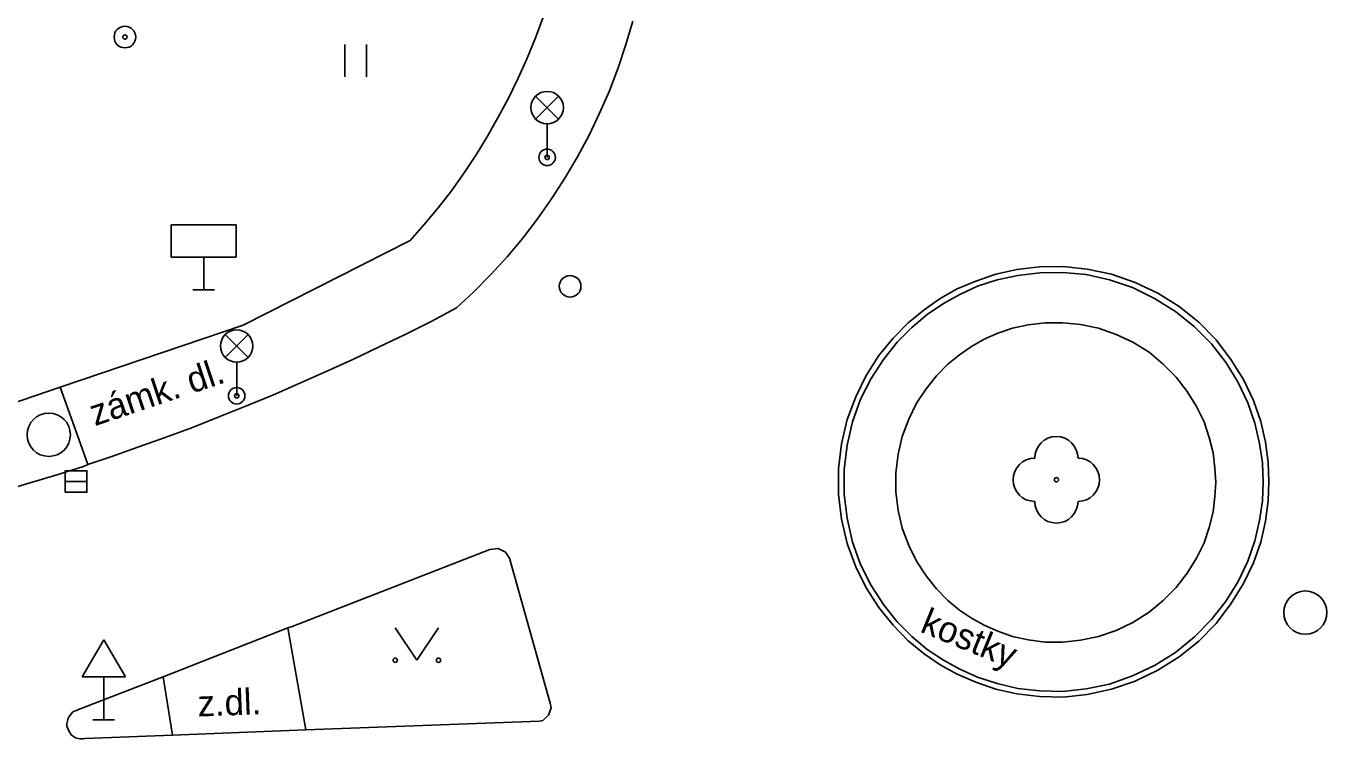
# Model space of a CAD drawing. Extents: x -493753 to -49290, y -1127285 to -112654.
# Drawn here: x -493551.62 to -493521.58, y -1126786.62 to -1126770.15 of the extents above; entities that cross this region are included whole.
import ezdxf

# ---------------------------------------------------------------- set-up
doc = ezdxf.new("R2010")
doc.units = 0
for name, color, linetype in [('Vrstva 10', 7, 'Continuous'), ('Vrstva 11', 7, 'Continuous'), ('Vrstva 22', 7, 'Continuous'), ('Vrstva 25', 7, 'Continuous'), ('Vrstva 27', 7, 'Continuous'), ('Vrstva 31', 7, 'Continuous'), ('Vrstva 33', 7, 'Continuous'), ('Vrstva 34', 7, 'Continuous'), ('Vrstva 36', 7, 'Continuous'), ('Vrstva 40', 7, 'Continuous')]:
    doc.layers.add(name, color=color, linetype=linetype)

msp = doc.modelspace()

# ---------------------------------------------------------------- linework, layer by layer
at = {"layer": 'Vrstva 10'}
for p, q in [((-493539.86, -1126770.42), (-493539.68, -1126769.94)), ((-493537.77, -1126770.57), (-493537.61, -1126770.03)), ((-493540.05, -1126770.89), (-493539.86, -1126770.42)), ((-493537.95, -1126771.11), (-493537.77, -1126770.57)), ((-493540.26, -1126771.35), (-493540.05, -1126770.89)), ((-493538.15, -1126771.64), (-493537.95, -1126771.11)), ((-493540.48, -1126771.81), (-493540.26, -1126771.35)), ((-493540.72, -1126772.25), (-493540.48, -1126771.81)), ((-493538.38, -1126772.16), (-493538.15, -1126771.64)), ((-493538.62, -1126772.67), (-493538.38, -1126772.16)), ((-493540.97, -1126772.69), (-493540.72, -1126772.25)), ((-493541.23, -1126773.12), (-493540.97, -1126772.69)), ((-493538.89, -1126773.17), (-493538.62, -1126772.67)), ((-493541.51, -1126773.54), (-493541.23, -1126773.12)), ((-493539.18, -1126773.66), (-493538.89, -1126773.17)), ((-493541.8, -1126773.95), (-493541.51, -1126773.54)), ((-493539.49, -1126774.14), (-493539.18, -1126773.66)), ((-493542.11, -1126774.35), (-493541.8, -1126773.95)), ((-493539.81, -1126774.6), (-493539.49, -1126774.14)), ((-493542.43, -1126774.73), (-493542.11, -1126774.35)), ((-493540.15, -1126775.05), (-493539.81, -1126774.6)), ((-493542.75, -1126775.1), (-493542.43, -1126774.73)), ((-493546.61, -1126777.06), (-493542.75, -1126775.1)), ((-493540.51, -1126775.48), (-493540.15, -1126775.05)), ((-493540.89, -1126775.89), (-493540.51, -1126775.48)), ((-493528.74, -1126775.77), (-493529.23, -1126775.88)), ((-493528.22, -1126775.71), (-493528.74, -1126775.77)), ((-493527.67, -1126775.7), (-493528.22, -1126775.71)), ((-493527.12, -1126775.76), (-493527.67, -1126775.7)), ((-493526.56, -1126775.88), (-493527.12, -1126775.76)), ((-493541.28, -1126776.29), (-493540.89, -1126775.89)), ((-493529.69, -1126776.04), (-493530.12, -1126776.22)), ((-493529.23, -1126775.88), (-493529.69, -1126776.04)), ((-493526.01, -1126776.07), (-493526.56, -1126775.88)), ((-493525.49, -1126776.32), (-493526.01, -1126776.07)), ((-493541.68, -1126776.66), (-493541.28, -1126776.29)), ((-493530.12, -1126776.22), (-493530.51, -1126776.44)), ((-493524.99, -1126776.63), (-493525.49, -1126776.32)), ((-493542.27, -1126776.97), (-493541.68, -1126776.66)), ((-493530.88, -1126776.7), (-493531.25, -1126777)), ((-493530.51, -1126776.44), (-493530.88, -1126776.7)), ((-493524.54, -1126776.99), (-493524.99, -1126776.63)), ((-493542.87, -1126777.27), (-493542.27, -1126776.97)), ((-493531.25, -1126777), (-493531.6, -1126777.36)), ((-493528.09, -1126777), (-493528.48, -1126777.05)), ((-493527.68, -1126777), (-493528.09, -1126777)), ((-493527.27, -1126777.04), (-493527.68, -1126777)), ((-493524.14, -1126777.4), (-493524.54, -1126776.99)), ((-493550.84, -1126778.49), (-493546.61, -1126777.06)), ((-493543.47, -1126777.56), (-493542.87, -1126777.27)), ((-493529.18, -1126777.24), (-493529.5, -1126777.38)), ((-493528.84, -1126777.13), (-493529.18, -1126777.24)), ((-493528.48, -1126777.05), (-493528.84, -1126777.13)), ((-493526.86, -1126777.13), (-493527.27, -1126777.04)), ((-493526.45, -1126777.27), (-493526.86, -1126777.13)), ((-493526.06, -1126777.45), (-493526.45, -1126777.27)), ((-493544.08, -1126777.85), (-493543.47, -1126777.56)), ((-493531.6, -1126777.36), (-493531.93, -1126777.76)), ((-493529.79, -1126777.55), (-493530.07, -1126777.74)), ((-493529.5, -1126777.38), (-493529.79, -1126777.55)), ((-493525.69, -1126777.68), (-493526.06, -1126777.45)), ((-493523.8, -1126777.85), (-493524.14, -1126777.4)), ((-493544.69, -1126778.13), (-493544.08, -1126777.85)), ((-493531.93, -1126777.76), (-493532.22, -1126778.22)), ((-493530.07, -1126777.74), (-493530.34, -1126777.96)), ((-493525.36, -1126777.96), (-493525.69, -1126777.68)), ((-493523.51, -1126778.31), (-493523.8, -1126777.85)), ((-493545.3, -1126778.4), (-493544.69, -1126778.13)), ((-493532.22, -1126778.22), (-493532.46, -1126778.71)), ((-493530.6, -1126778.23), (-493530.84, -1126778.53)), ((-493530.34, -1126777.96), (-493530.6, -1126778.23)), ((-493525.06, -1126778.26), (-493525.36, -1126777.96)), ((-493554.13, -1126779.61), (-493550.84, -1126778.49)), ((-493545.91, -1126778.67), (-493545.3, -1126778.4)), ((-493530.84, -1126778.53), (-493531.06, -1126778.86)), ((-493524.81, -1126778.59), (-493525.06, -1126778.26)), ((-493523.28, -1126778.8), (-493523.51, -1126778.31)), ((-493546.53, -1126778.92), (-493545.91, -1126778.67)), ((-493532.46, -1126778.71), (-493532.66, -1126779.24)), ((-493524.59, -1126778.94), (-493524.81, -1126778.59)), ((-493523.11, -1126779.28), (-493523.28, -1126778.8)), ((-493547.15, -1126779.17), (-493546.53, -1126778.92)), ((-493531.06, -1126778.86), (-493531.24, -1126779.23)), ((-493524.42, -1126779.29), (-493524.59, -1126778.94)), ((-493548.41, -1126779.65), (-493547.78, -1126779.42)), ((-493547.78, -1126779.42), (-493547.15, -1126779.17)), ((-493532.66, -1126779.24), (-493532.79, -1126779.8)), ((-493531.24, -1126779.23), (-493531.39, -1126779.63)), ((-493524.3, -1126779.65), (-493524.42, -1126779.29)), ((-493523, -1126779.76), (-493523.11, -1126779.28)), ((-493549.04, -1126779.88), (-493548.41, -1126779.65)), ((-493531.39, -1126779.63), (-493531.48, -1126780.04)), ((-493524.21, -1126780.01), (-493524.3, -1126779.65)), ((-493549.67, -1126780.1), (-493549.04, -1126779.88)), ((-493532.79, -1126779.8), (-493532.86, -1126780.38)), ((-493524.17, -1126780.36), (-493524.21, -1126780.01)), ((-493522.94, -1126780.23), (-493523, -1126779.76)), ((-493550.94, -1126780.52), (-493550.3, -1126780.32)), ((-493531.48, -1126780.04), (-493531.54, -1126780.47)), ((-493522.92, -1126780.67), (-493522.94, -1126780.23)), ((-493551.58, -1126780.72), (-493550.94, -1126780.52)), ((-493532.86, -1126780.38), (-493532.86, -1126780.97)), ((-493531.54, -1126780.47), (-493531.54, -1126780.91)), ((-493524.15, -1126780.69), (-493524.17, -1126780.36)), ((-493552.22, -1126780.91), (-493551.58, -1126780.72)), ((-493531.54, -1126780.91), (-493531.48, -1126781.34)), ((-493524.17, -1126781.02), (-493524.15, -1126780.69)), ((-493522.94, -1126781.12), (-493522.92, -1126780.67)), ((-493532.86, -1126780.97), (-493532.79, -1126781.54)), ((-493524.21, -1126781.37), (-493524.17, -1126781.02)), ((-493523, -1126781.59), (-493522.94, -1126781.12)), ((-493532.79, -1126781.54), (-493532.66, -1126782.1)), ((-493531.48, -1126781.34), (-493531.39, -1126781.75)), ((-493524.3, -1126781.73), (-493524.21, -1126781.37)), ((-493531.39, -1126781.75), (-493531.24, -1126782.15)), ((-493524.42, -1126782.09), (-493524.3, -1126781.73)), ((-493523.11, -1126782.07), (-493523, -1126781.59)), ((-493532.66, -1126782.1), (-493532.46, -1126782.64)), ((-493524.59, -1126782.44), (-493524.42, -1126782.09)), ((-493523.28, -1126782.55), (-493523.11, -1126782.07)), ((-493531.24, -1126782.15), (-493531.06, -1126782.51)), ((-493524.81, -1126782.79), (-493524.59, -1126782.44)), ((-493532.46, -1126782.64), (-493532.22, -1126783.13)), ((-493531.06, -1126782.51), (-493530.84, -1126782.85)), ((-493523.51, -1126783.03), (-493523.28, -1126782.55)), ((-493530.84, -1126782.85), (-493530.6, -1126783.15)), ((-493525.06, -1126783.12), (-493524.81, -1126782.79)), ((-493523.8, -1126783.5), (-493523.51, -1126783.03)), ((-493532.22, -1126783.13), (-493531.93, -1126783.58)), ((-493530.6, -1126783.15), (-493530.34, -1126783.42)), ((-493525.36, -1126783.42), (-493525.06, -1126783.12)), ((-493531.93, -1126783.58), (-493531.6, -1126783.99)), ((-493530.34, -1126783.42), (-493530.07, -1126783.64)), ((-493530.07, -1126783.64), (-493529.79, -1126783.83)), ((-493525.69, -1126783.69), (-493525.36, -1126783.42)), ((-493524.14, -1126783.95), (-493523.8, -1126783.5)), ((-493529.79, -1126783.83), (-493529.5, -1126783.99)), ((-493526.45, -1126784.11), (-493526.06, -1126783.93)), ((-493526.06, -1126783.93), (-493525.69, -1126783.69)), ((-493548.46, -1126785.18), (-493545.58, -1126784.05)), ((-493545.48, -1126784.02), (-493545.58, -1126784.05)), ((-493545.16, -1126786.41), (-493545.58, -1126784.05)), ((-493531.6, -1126783.99), (-493531.25, -1126784.35)), ((-493529.5, -1126783.99), (-493529.18, -1126784.13)), ((-493529.18, -1126784.13), (-493528.84, -1126784.25)), ((-493526.86, -1126784.25), (-493526.45, -1126784.11)), ((-493524.54, -1126784.36), (-493524.14, -1126783.95)), ((-493531.25, -1126784.35), (-493530.88, -1126784.65)), ((-493528.84, -1126784.25), (-493528.48, -1126784.33)), ((-493528.48, -1126784.33), (-493528.09, -1126784.38)), ((-493528.09, -1126784.38), (-493527.68, -1126784.38)), ((-493527.68, -1126784.38), (-493527.27, -1126784.34)), ((-493527.27, -1126784.34), (-493526.86, -1126784.25)), ((-493524.99, -1126784.72), (-493524.54, -1126784.36)), ((-493530.88, -1126784.65), (-493530.51, -1126784.91)), ((-493525.49, -1126785.03), (-493524.99, -1126784.72)), ((-493530.51, -1126784.91), (-493530.12, -1126785.12)), ((-493530.12, -1126785.12), (-493529.69, -1126785.31)), ((-493526.01, -1126785.28), (-493525.49, -1126785.03)), ((-493548.46, -1126785.18), (-493550.41, -1126785.94)), ((-493548.24, -1126786.53), (-493548.46, -1126785.18)), ((-493529.69, -1126785.31), (-493529.23, -1126785.47)), ((-493526.56, -1126785.47), (-493526.01, -1126785.28)), ((-493529.23, -1126785.47), (-493528.74, -1126785.58)), ((-493528.74, -1126785.58), (-493528.22, -1126785.64)), ((-493528.22, -1126785.64), (-493527.67, -1126785.65)), ((-493527.67, -1126785.65), (-493527.12, -1126785.59)), ((-493527.12, -1126785.59), (-493526.56, -1126785.47)), ((-493550.56, -1126786.01), (-493550.6, -1126786.06)), ((-493550.51, -1126785.98), (-493550.56, -1126786.01)), ((-493550.46, -1126785.96), (-493550.51, -1126785.98)), ((-493550.41, -1126785.94), (-493550.46, -1126785.96)), ((-493550.67, -1126786.21), (-493550.68, -1126786.27)), ((-493550.68, -1126786.27), (-493550.68, -1126786.32)), ((-493550.68, -1126786.32), (-493550.66, -1126786.38)), ((-493550.66, -1126786.16), (-493550.67, -1126786.21)), ((-493550.63, -1126786.1), (-493550.66, -1126786.16)), ((-493550.6, -1126786.06), (-493550.63, -1126786.1)), ((-493539.77, -1126786.21), (-493545.16, -1126786.41)), ((-493550.66, -1126786.38), (-493550.64, -1126786.43)), ((-493550.64, -1126786.43), (-493550.58, -1126786.52)), ((-493550.58, -1126786.52), (-493550.53, -1126786.56)), ((-493550.53, -1126786.56), (-493550.48, -1126786.59)), ((-493550.48, -1126786.59), (-493550.42, -1126786.61)), ((-493550.42, -1126786.61), (-493550.37, -1126786.62)), ((-493550.37, -1126786.62), (-493550.31, -1126786.62)), ((-493550.31, -1126786.62), (-493550.26, -1126786.61)), ((-493548.24, -1126786.53), (-493550.26, -1126786.61)), ((-493545.16, -1126786.41), (-493548.24, -1126786.53))]:
    msp.add_line(p, q, dxfattribs=at)
for points in [[(-493550.3, -1126780.32), (-493550.2, -1126780.28), (-493549.67, -1126780.1)], [(-493540.46, -1126782.44), (-493540.55, -1126782.3), (-493540.72, -1126782.22), (-493540.91, -1126782.24), (-493545.48, -1126784.02)], [(-493540.46, -1126782.44), (-493539.52, -1126785.79), (-493539.5, -1126785.9), (-493539.56, -1126786.07), (-493539.69, -1126786.19), (-493539.77, -1126786.21)]]:
    msp.add_lwpolyline(points, dxfattribs=at)
at = {"layer": 'Vrstva 11'}
for p, q in [((-493529.2, -1126776.01), (-493529.65, -1126776.16)), ((-493528.72, -1126775.91), (-493529.2, -1126776.01)), ((-493528.21, -1126775.85), (-493528.72, -1126775.91)), ((-493527.68, -1126775.84), (-493528.21, -1126775.85)), ((-493527.14, -1126775.89), (-493527.68, -1126775.84)), ((-493526.6, -1126776.01), (-493527.14, -1126775.89)), ((-493526.07, -1126776.19), (-493526.6, -1126776.01)), ((-493530.06, -1126776.35), (-493530.44, -1126776.56)), ((-493529.65, -1126776.16), (-493530.06, -1126776.35)), ((-493525.56, -1126776.44), (-493526.07, -1126776.19)), ((-493530.44, -1126776.56), (-493530.81, -1126776.81)), ((-493525.08, -1126776.74), (-493525.56, -1126776.44)), ((-493530.81, -1126776.81), (-493531.17, -1126777.11)), ((-493524.64, -1126777.1), (-493525.08, -1126776.74)), ((-493531.17, -1126777.11), (-493531.51, -1126777.45)), ((-493524.25, -1126777.49), (-493524.64, -1126777.1)), ((-493531.51, -1126777.45), (-493531.82, -1126777.85)), ((-493523.91, -1126777.93), (-493524.25, -1126777.49)), ((-493531.82, -1126777.85), (-493532.11, -1126778.29)), ((-493523.63, -1126778.38), (-493523.91, -1126777.93)), ((-493550.37, -1126779.8), (-493550.84, -1126778.49)), ((-493532.11, -1126778.29), (-493532.35, -1126778.77)), ((-493523.41, -1126778.85), (-493523.63, -1126778.38)), ((-493532.35, -1126778.77), (-493532.54, -1126779.29)), ((-493523.25, -1126779.32), (-493523.41, -1126778.85)), ((-493532.54, -1126779.29), (-493532.66, -1126779.83)), ((-493523.14, -1126779.79), (-493523.25, -1126779.32)), ((-493550.37, -1126779.8), (-493550.2, -1126780.28)), ((-493532.66, -1126779.83), (-493532.73, -1126780.39)), ((-493523.07, -1126780.24), (-493523.14, -1126779.79)), ((-493523.05, -1126780.68), (-493523.07, -1126780.24)), ((-493532.73, -1126780.39), (-493532.73, -1126780.96)), ((-493523.07, -1126781.12), (-493523.05, -1126780.68)), ((-493532.73, -1126780.96), (-493532.66, -1126781.52)), ((-493523.14, -1126781.57), (-493523.07, -1126781.12)), ((-493532.66, -1126781.52), (-493532.54, -1126782.07)), ((-493523.25, -1126782.04), (-493523.14, -1126781.57)), ((-493532.54, -1126782.07), (-493532.35, -1126782.59)), ((-493523.41, -1126782.51), (-493523.25, -1126782.04)), ((-493532.35, -1126782.59), (-493532.11, -1126783.07)), ((-493523.63, -1126782.98), (-493523.41, -1126782.51)), ((-493523.91, -1126783.43), (-493523.63, -1126782.98)), ((-493532.11, -1126783.07), (-493531.82, -1126783.51)), ((-493531.82, -1126783.51), (-493531.51, -1126783.91)), ((-493524.25, -1126783.86), (-493523.91, -1126783.43)), ((-493531.51, -1126783.91), (-493531.17, -1126784.25)), ((-493524.64, -1126784.26), (-493524.25, -1126783.86)), ((-493531.17, -1126784.25), (-493530.81, -1126784.55)), ((-493525.08, -1126784.62), (-493524.64, -1126784.26)), ((-493530.81, -1126784.55), (-493530.44, -1126784.8)), ((-493530.44, -1126784.8), (-493530.06, -1126785.01)), ((-493525.56, -1126784.92), (-493525.08, -1126784.62)), ((-493530.06, -1126785.01), (-493529.65, -1126785.19)), ((-493526.07, -1126785.16), (-493525.56, -1126784.92)), ((-493529.65, -1126785.19), (-493529.2, -1126785.34)), ((-493529.2, -1126785.34), (-493528.72, -1126785.45)), ((-493527.14, -1126785.46), (-493526.6, -1126785.35)), ((-493526.6, -1126785.35), (-493526.07, -1126785.16)), ((-493528.72, -1126785.45), (-493528.21, -1126785.51)), ((-493528.21, -1126785.51), (-493527.68, -1126785.52)), ((-493527.68, -1126785.52), (-493527.14, -1126785.46))]:
    msp.add_line(p, q, dxfattribs=at)
at = {"layer": 'Vrstva 22'}
msp.add_circle((-493527.83, -1126780.63), 0.05, dxfattribs=at)
for centre, start, end in [((-493527.83, -1126780.13), 0, 180), ((-493528.33, -1126780.63), 90, 270), ((-493527.33, -1126780.63), 270, 90), ((-493527.83, -1126781.13), 180, 0)]:
    msp.add_arc(centre, 0.5, start, end, dxfattribs=at)
at = {"layer": 'Vrstva 25'}
for radius in [0.25, 0.05]:
    msp.add_circle((-493549.34, -1126770.4), radius, dxfattribs=at)
at = {"layer": 'Vrstva 27'}
msp.add_line((-493550.72, -1126780.67), (-493550.22, -1126780.67), dxfattribs=at)
msp.add_lwpolyline([(-493550.72, -1126780.92), (-493550.22, -1126780.92), (-493550.22, -1126780.42), (-493550.72, -1126780.42)], close=True, dxfattribs=at)
for centre in [(-493551.1, -1126779.59), (-493522.08, -1126783.7)]:
    msp.add_circle(centre, 0.5, dxfattribs=at)
at = {"layer": 'Vrstva 31'}
msp.add_circle((-493539.06, -1126776.16), 0.25, dxfattribs=at)
at = {"layer": 'Vrstva 33'}
for p, q in [((-493539.855, -1126771.765), (-493539.325, -1126772.295)), ((-493539.855, -1126772.295), (-493539.325, -1126771.765)), ((-493539.59, -1126773.18), (-493539.59, -1126772.405)), ((-493547.025, -1126777.275), (-493546.495, -1126777.805)), ((-493547.025, -1126777.805), (-493546.495, -1126777.275)), ((-493546.76, -1126778.69), (-493546.76, -1126777.915))]:
    msp.add_line(p, q, dxfattribs=at)
for centre, radius in [((-493539.59, -1126772.03), 0.375), ((-493539.59, -1126773.18), 0.19), ((-493539.59, -1126773.18), 0.05), ((-493546.76, -1126777.54), 0.375), ((-493546.76, -1126778.69), 0.19), ((-493546.76, -1126778.69), 0.05)]:
    msp.add_circle(centre, radius, dxfattribs=at)
at = {"layer": 'Vrstva 34'}
for p, q in [((-493548.27, -1126774.74), (-493546.77, -1126774.74)), ((-493548.27, -1126775.49), (-493548.27, -1126774.74)), ((-493546.77, -1126774.74), (-493546.77, -1126775.49)), ((-493546.77, -1126775.49), (-493548.27, -1126775.49)), ((-493547.52, -1126775.49), (-493547.52, -1126776.24)), ((-493547.77, -1126776.24), (-493547.27, -1126776.24)), ((-493550.33, -1126785.18), (-493549.83, -1126784.33)), ((-493549.83, -1126784.33), (-493549.33, -1126785.18)), ((-493550.33, -1126785.18), (-493549.33, -1126785.18)), ((-493549.83, -1126786.18), (-493549.83, -1126785.18)), ((-493550.08, -1126786.18), (-493549.58, -1126786.18))]:
    msp.add_line(p, q, dxfattribs=at)
at = {"layer": 'Vrstva 36'}
for p, q in [((-493544.26, -1126771.32), (-493544.26, -1126770.57)), ((-493543.76, -1126771.32), (-493543.76, -1126770.57)), ((-493543.1, -1126784.05), (-493542.6, -1126784.8)), ((-493542.6, -1126784.8), (-493542.1, -1126784.05))]:
    msp.add_line(p, q, dxfattribs=at)
for centre in [(-493543.099, -1126784.8), (-493542.099, -1126784.8)]:
    msp.add_circle(centre, 0.05, dxfattribs=at)

# ---------------------------------------------------------------- texts
at = {"layer": 'Vrstva 40'}
for s, rotation, p in [('zámk. dl.', 18.5209, (-493550.036, -1126779.392)), ('kostky', 337.7578, (-493531.002, -1126784.134)), ('z.dl.', 2.2312, (-493547.653, -1126786.102))]:
    msp.add_text(s, height=0.6, rotation=rotation, dxfattribs=at).set_placement(p)

doc.saveas('drawing.dxf')
